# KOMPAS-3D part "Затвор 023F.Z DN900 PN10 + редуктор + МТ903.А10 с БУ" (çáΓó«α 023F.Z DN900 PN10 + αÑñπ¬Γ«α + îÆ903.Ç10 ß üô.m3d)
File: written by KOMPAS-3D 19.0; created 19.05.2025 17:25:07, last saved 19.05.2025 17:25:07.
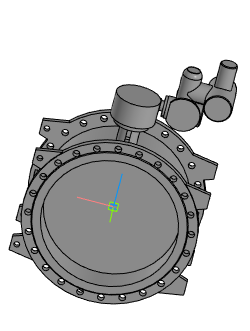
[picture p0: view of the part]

Document properties: Полное имя файла: Затвор 023F.Z DN900 PN10 + редуктор + МТ903.А10 с БУ.a3d

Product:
- Part/product: Затвор 023F.Z DN900 PN10 + редуктор + МТ903.А10 с БУ
    Масса: 911.303

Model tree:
1. Операция без истории:1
